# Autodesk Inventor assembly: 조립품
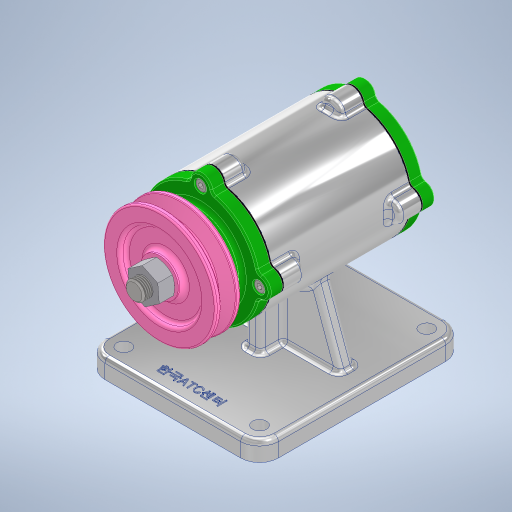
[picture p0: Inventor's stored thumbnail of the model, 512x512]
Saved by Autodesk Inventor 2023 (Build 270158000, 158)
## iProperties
Created: 2023-08
Part Number: 조립품
Document SubType Name: Assembly
Designer: asung
Author: asung
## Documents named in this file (12)
- C:\Users\asung\Desktop\730808V1002\조립품.iam
- C:\Users\asung\Desktop\730808V1002\본체.ipt
- C:\Users\asung\Desktop\730808V1002\개스킷.ipt
- C:\Users\asung\Desktop\730808V1002\뒤커버.ipt
- C:\Users\asung\Desktop\730808V1002\베어링 6204.ipt
- C:\Users\asung\Desktop\730808V1002\앞커버.ipt
- C:\Users\asung\Desktop\730808V1002\오일 실.ipt
- C:\Users\asung\Desktop\730808V1002\V-벨트풀리.ipt
- C:\Users\asung\Desktop\730808V1002\너트 M12 x 1.25.ipt
- C:\Users\asung\Desktop\730808V1002\볼트 M4 x 12.ipt
- C:\Users\asung\Desktop\730808V1002\축.ipt
- C:\Users\asung\Desktop\730808V1002\키 4 x 4.ipt
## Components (8 placed, 6 different names)
1. 개스킷:1
2. KS B 2023 6204 - 20 x 47 x 14:1
3. 개스킷:2
4. KS B 2023 6204 - 20 x 47 x 14:2
5. KS B 2804 D D - 20 32 8:2
6. V-벨트풀리:1
7. KS B 1012 클래스 1 일반 - 미터 M12x1.25:1
8. KS B 1311 (I) 4 x 4 x 12:1
